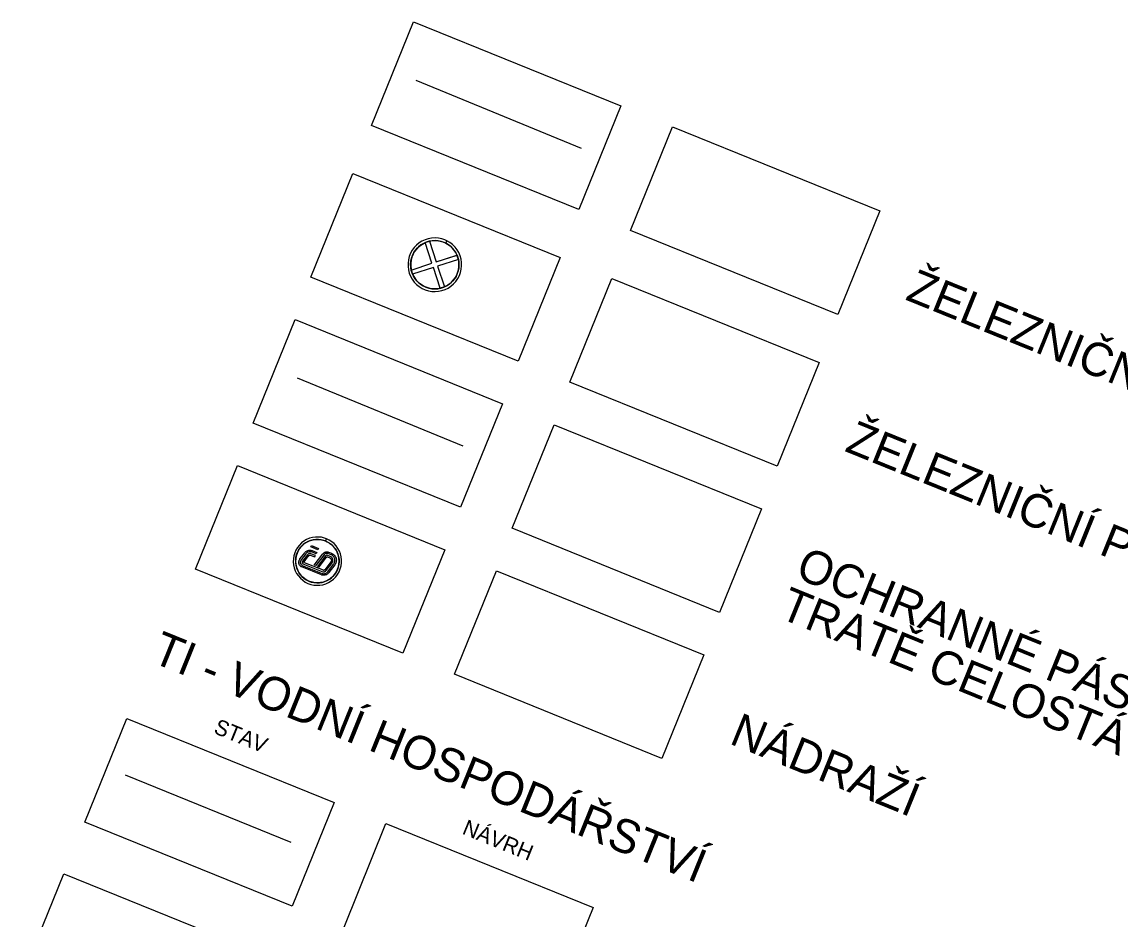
# Model space of a CAD drawing. Extents: x -522797 to -519326, y -1191143 to -1184078.
# Drawn here: x -521504.4 to -521013.3, y -1189290.3 to -1188889.1 of the extents above; entities that cross this region are included whole.
import ezdxf

# ---------------------------------------------------------------- set-up
doc = ezdxf.new("R2010")
doc.units = 0
for name, color, linetype in [('Implicitní', 7, 'Continuous'), ('nadrazi_s', 7, 'Continuous'), ('OP_zel_trate_s', 7, 'Continuous'), ('zel_celostat_s', 7, 'Continuous'), ('zel_prejezd_s', 7, 'Continuous')]:
    doc.layers.add(name, color=color, linetype=linetype)

msp = doc.modelspace()

# ---------------------------------------------------------------- linework, layer by layer
at = {"layer": 'Implicitní'}
msp.add_line((-521458.26, -1189225.9), (-521384.11, -1189255.95), dxfattribs=at)
for points in [[(-521329.25, -1188889.13), (-521236.57, -1188926.69), (-521255.35, -1188973.03), (-521348.03, -1188935.47)], [(-521213.4, -1188936.09), (-521120.73, -1188973.65), (-521139.51, -1189019.99), (-521232.18, -1188982.42)], [(-521356.37, -1188956.93), (-521263.68, -1188994.47), (-521282.45, -1189040.81), (-521375.14, -1189003.27)], [(-521240.51, -1189003.86), (-521147.82, -1189041.4), (-521166.6, -1189087.74), (-521259.28, -1189050.2)], [(-521382.14, -1189022.23), (-521289.49, -1189059.85), (-521308.3, -1189106.18), (-521400.95, -1189068.56)], [(-521266.32, -1189069.26), (-521173.67, -1189106.88), (-521192.48, -1189153.2), (-521285.13, -1189115.58)], [(-521407.91, -1189087.53), (-521315.26, -1189125.15), (-521334.07, -1189171.48), (-521426.72, -1189133.86)], [(-521292.1, -1189134.56), (-521199.44, -1189172.18), (-521218.25, -1189218.51), (-521310.91, -1189180.88)], [(-521457.41, -1189200.67), (-521364.73, -1189238.23), (-521383.51, -1189284.57), (-521476.19, -1189247.01)], [(-521341.56, -1189247.62), (-521248.89, -1189285.18), (-521267.67, -1189331.52), (-521360.34, -1189293.96)], [(-521485.58, -1189270.18), (-521392.9, -1189307.74), (-521411.68, -1189354.08), (-521504.36, -1189316.52)]]:
    msp.add_lwpolyline(points, close=True, dxfattribs=at)
at = {"layer": 'nadrazi_s'}
for points in [[(-521368.23, -1189120.23), (-521369.08, -1189119.93), (-521370.41, -1189119.61), (-521371.76, -1189119.47), (-521373.13, -1189119.5), (-521374.48, -1189119.69), (-521375.8, -1189120.06), (-521377.06, -1189120.59), (-521378.24, -1189121.28), (-521379.33, -1189122.11), (-521380.3, -1189123.07), (-521381.14, -1189124.14), (-521381.84, -1189125.31), (-521382.39, -1189126.56), (-521382.78, -1189127.88), (-521382.99, -1189129.22), (-521383.04, -1189130.59), (-521382.91, -1189131.95), (-521382.62, -1189133.28), (-521382.15, -1189134.57), (-521381.53, -1189135.78), (-521380.76, -1189136.91), (-521379.85, -1189137.93), (-521378.82, -1189138.83), (-521377.69, -1189139.6), (-521376.47, -1189140.21), (-521375.18, -1189140.66), (-521373.84, -1189140.95), (-521372.48, -1189141.07), (-521371.12, -1189141.01), (-521369.77, -1189140.79), (-521368.46, -1189140.39), (-521367.21, -1189139.83), (-521366.05, -1189139.12), (-521364.98, -1189138.27), (-521364.03, -1189137.29), (-521363.21, -1189136.2), (-521362.53, -1189135.01), (-521362.01, -1189133.75), (-521361.65, -1189132.43), (-521361.46, -1189131.08), (-521361.44, -1189129.71), (-521361.6, -1189128.35), (-521361.93, -1189127.03), (-521362.42, -1189125.75), (-521363.07, -1189124.55), (-521363.86, -1189123.44), (-521364.79, -1189122.43), (-521365.84, -1189121.56), (-521366.99, -1189120.82), (-521368.22, -1189120.23)], [(-521363.21, -1189133.88), (-521362.82, -1189132.71), (-521362.59, -1189131.5), (-521362.51, -1189130.27), (-521362.59, -1189129.05), (-521362.82, -1189127.84), (-521363.2, -1189126.67), (-521363.73, -1189125.56), (-521364.39, -1189124.52), (-521365.17, -1189123.58), (-521366.07, -1189122.74), (-521367.07, -1189122.02), (-521368.15, -1189121.44), (-521369.3, -1189120.99), (-521370.49, -1189120.69), (-521371.72, -1189120.55), (-521372.95, -1189120.56), (-521374.16, -1189120.73), (-521375.35, -1189121.05), (-521376.49, -1189121.52), (-521377.56, -1189122.12), (-521378.54, -1189122.86), (-521379.43, -1189123.71), (-521380.2, -1189124.67), (-521380.84, -1189125.72), (-521381.34, -1189126.84), (-521381.7, -1189128.02), (-521381.91, -1189129.23), (-521381.96, -1189130.46), (-521381.86, -1189131.69), (-521381.6, -1189132.89), (-521381.2, -1189134.05), (-521380.65, -1189135.15), (-521379.96, -1189136.17), (-521379.16, -1189137.1), (-521378.24, -1189137.92), (-521377.23, -1189138.62), (-521376.13, -1189139.18), (-521374.98, -1189139.6), (-521373.78, -1189139.87), (-521372.55, -1189139.99), (-521371.32, -1189139.95), (-521370.11, -1189139.76), (-521368.93, -1189139.41), (-521367.8, -1189138.92), (-521366.74, -1189138.29), (-521365.78, -1189137.53), (-521364.91, -1189136.66), (-521364.16, -1189135.69), (-521363.54, -1189134.62), (-521363.21, -1189133.88)], [(-521368.62, -1189121.23), (-521367.88, -1189121.57), (-521366.82, -1189122.19), (-521365.85, -1189122.93), (-521364.97, -1189123.8), (-521364.21, -1189124.77), (-521363.58, -1189125.82), (-521363.09, -1189126.95), (-521362.75, -1189128.13), (-521362.55, -1189129.35), (-521362.52, -1189130.58), (-521362.63, -1189131.8), (-521362.9, -1189133), (-521363.32, -1189134.16), (-521363.88, -1189135.25), (-521364.58, -1189136.26), (-521365.4, -1189137.18), (-521366.33, -1189137.99), (-521367.35, -1189138.67), (-521368.45, -1189139.22), (-521369.61, -1189139.63), (-521370.81, -1189139.89), (-521372.04, -1189139.99), (-521373.27, -1189139.94), (-521374.48, -1189139.73), (-521375.65, -1189139.37), (-521376.78, -1189138.87), (-521377.82, -1189138.23), (-521378.79, -1189137.46), (-521379.64, -1189136.58), (-521380.38, -1189135.59), (-521380.98, -1189134.52), (-521381.45, -1189133.38), (-521381.77, -1189132.2), (-521381.94, -1189130.98), (-521381.95, -1189129.75), (-521381.81, -1189128.53), (-521381.51, -1189127.33), (-521381.07, -1189126.19), (-521380.48, -1189125.1), (-521379.77, -1189124.11), (-521378.93, -1189123.2), (-521377.98, -1189122.42), (-521376.95, -1189121.75), (-521375.84, -1189121.23), (-521374.67, -1189120.85), (-521373.46, -1189120.61), (-521372.23, -1189120.54), (-521371.01, -1189120.62), (-521369.8, -1189120.85), (-521368.63, -1189121.23)], [(-521368.63, -1189121.23), (-521368.23, -1189120.23)], [(-521368.22, -1189120.23), (-521368.62, -1189121.23)], [(-521380.03, -1189129.3), (-521377.89, -1189126.52)], [(-521377.36, -1189126.95), (-521379.5, -1189129.71)], [(-521376.68, -1189127.45), (-521378.85, -1189130.26)], [(-521378.19, -1189130.52), (-521376.17, -1189127.9)], [(-521377.89, -1189126.52), (-521377.65, -1189126.25), (-521377.39, -1189126), (-521377.1, -1189125.79), (-521376.79, -1189125.62), (-521376.47, -1189125.49), (-521376.13, -1189125.4), (-521375.8, -1189125.35), (-521375.46, -1189125.35), (-521375.12, -1189125.39), (-521374.8, -1189125.47), (-521374.64, -1189125.53)], [(-521374.89, -1189126.16), (-521375.13, -1189126.08), (-521375.38, -1189126.03), (-521375.63, -1189126.02), (-521375.88, -1189126.04), (-521376.14, -1189126.1), (-521376.38, -1189126.18), (-521376.62, -1189126.3), (-521376.85, -1189126.44), (-521377.06, -1189126.61), (-521377.25, -1189126.81), (-521377.36, -1189126.95)], [(-521375.21, -1189126.94), (-521375.21, -1189126.94), (-521375.34, -1189126.9), (-521375.49, -1189126.87), (-521375.63, -1189126.87), (-521375.78, -1189126.88), (-521375.93, -1189126.92), (-521376.07, -1189126.97), (-521376.22, -1189127.04), (-521376.35, -1189127.13), (-521376.48, -1189127.23), (-521376.6, -1189127.35), (-521376.68, -1189127.45)], [(-521376.17, -1189127.91), (-521376.17, -1189127.9), (-521376.12, -1189127.84), (-521376.07, -1189127.77), (-521376.01, -1189127.72), (-521375.95, -1189127.67), (-521375.89, -1189127.63), (-521375.83, -1189127.6), (-521375.76, -1189127.57), (-521375.7, -1189127.55), (-521375.64, -1189127.55), (-521375.58, -1189127.55), (-521375.52, -1189127.56), (-521375.47, -1189127.57)], [(-521375.47, -1189127.57), (-521373.38, -1189128.41)], [(-521373.13, -1189127.77), (-521375.21, -1189126.94)], [(-521372.07, -1189125.2), (-521375.2, -1189123.94), (-521374.94, -1189123.31), (-521371.81, -1189124.56), (-521372.07, -1189125.2)], [(-521372.81, -1189126.99), (-521374.89, -1189126.16)], [(-521374.64, -1189125.53), (-521372.56, -1189126.36)], [(-521374.64, -1189125.53), (-521374.64, -1189125.53)], [(-521373.62, -1189132.02), (-521369.75, -1189126.99)], [(-521373.38, -1189128.41), (-521373.13, -1189127.77)], [(-521369.22, -1189127.41), (-521372.97, -1189132.28)], [(-521372.56, -1189126.36), (-521372.81, -1189126.99)], [(-521368.56, -1189127.95), (-521372.15, -1189132.61)], [(-521369.75, -1189126.99), (-521369.57, -1189126.78), (-521369.36, -1189126.59), (-521369.14, -1189126.43), (-521368.9, -1189126.3), (-521368.66, -1189126.19), (-521368.4, -1189126.12), (-521368.14, -1189126.09), (-521367.88, -1189126.08), (-521367.62, -1189126.12), (-521367.37, -1189126.18), (-521367.25, -1189126.22)], [(-521367.5, -1189126.85), (-521367.66, -1189126.8), (-521367.84, -1189126.77), (-521368.01, -1189126.76), (-521368.19, -1189126.78), (-521368.36, -1189126.81), (-521368.53, -1189126.87), (-521368.7, -1189126.95), (-521368.86, -1189127.05), (-521369, -1189127.17), (-521369.14, -1189127.31), (-521369.22, -1189127.41)], [(-521367.82, -1189127.64), (-521367.85, -1189127.63), (-521367.91, -1189127.61), (-521367.98, -1189127.61), (-521368.05, -1189127.61), (-521368.12, -1189127.62), (-521368.19, -1189127.65), (-521368.26, -1189127.68), (-521368.33, -1189127.72), (-521368.39, -1189127.76), (-521368.45, -1189127.82), (-521368.51, -1189127.88), (-521368.56, -1189127.95)], [(-521366.46, -1189128.18), (-521367.81, -1189127.64)], [(-521366.14, -1189127.4), (-521367.5, -1189126.85)], [(-521367.25, -1189126.22), (-521365.89, -1189126.77)], [(-521365, -1189131.57), (-521364.81, -1189131.29), (-521364.65, -1189130.98), (-521364.54, -1189130.66), (-521364.47, -1189130.32), (-521364.44, -1189129.98), (-521364.45, -1189129.64), (-521364.51, -1189129.3), (-521364.61, -1189128.97), (-521364.75, -1189128.66), (-521364.92, -1189128.36), (-521365.14, -1189128.1), (-521365.38, -1189127.86), (-521365.66, -1189127.65), (-521365.96, -1189127.48), (-521366.14, -1189127.4)], [(-521365.89, -1189126.77), (-521365.5, -1189126.95), (-521365.14, -1189127.18), (-521364.81, -1189127.46), (-521364.52, -1189127.77), (-521364.27, -1189128.12), (-521364.07, -1189128.5), (-521363.91, -1189128.9), (-521363.81, -1189129.32), (-521363.76, -1189129.74), (-521363.77, -1189130.17), (-521363.83, -1189130.6), (-521363.94, -1189131.01), (-521364.1, -1189131.41), (-521364.31, -1189131.78), (-521364.46, -1189131.99)], [(-521379.26, -1189132.85), (-521379.49, -1189132.74), (-521379.71, -1189132.6), (-521379.91, -1189132.43), (-521380.08, -1189132.24), (-521380.23, -1189132.02), (-521380.36, -1189131.78), (-521380.45, -1189131.53), (-521380.52, -1189131.26), (-521380.55, -1189130.99), (-521380.55, -1189130.71), (-521380.52, -1189130.43), (-521380.46, -1189130.16), (-521380.37, -1189129.89), (-521380.25, -1189129.64), (-521380.11, -1189129.4), (-521380.03, -1189129.3)], [(-521379.51, -1189129.73), (-521379.61, -1189129.89), (-521379.71, -1189130.06), (-521379.78, -1189130.24), (-521379.83, -1189130.43), (-521379.87, -1189130.62), (-521379.88, -1189130.82), (-521379.87, -1189131.01), (-521379.84, -1189131.19), (-521379.79, -1189131.37), (-521379.72, -1189131.54), (-521379.63, -1189131.7), (-521379.53, -1189131.84), (-521379.41, -1189131.97), (-521379.27, -1189132.08), (-521379.12, -1189132.17), (-521379.01, -1189132.22)], [(-521370.36, -1189136.42), (-521379.26, -1189132.86)], [(-521378.85, -1189130.26), (-521378.89, -1189130.33), (-521378.93, -1189130.41), (-521378.97, -1189130.49), (-521378.99, -1189130.58), (-521379.01, -1189130.66), (-521379.03, -1189130.75), (-521379.03, -1189130.83), (-521379.03, -1189130.91), (-521379.02, -1189130.99), (-521379, -1189131.07), (-521378.97, -1189131.14), (-521378.94, -1189131.21), (-521378.9, -1189131.27), (-521378.86, -1189131.32), (-521378.81, -1189131.37), (-521378.75, -1189131.41), (-521378.69, -1189131.44)], [(-521379.01, -1189132.23), (-521370.11, -1189135.79)], [(-521378.69, -1189131.44), (-521369.79, -1189135)], [(-521378.07, -1189130.96), (-521378.09, -1189130.95), (-521378.12, -1189130.93), (-521378.15, -1189130.91), (-521378.17, -1189130.88), (-521378.2, -1189130.85), (-521378.21, -1189130.82), (-521378.23, -1189130.79), (-521378.24, -1189130.76), (-521378.25, -1189130.72), (-521378.25, -1189130.69), (-521378.24, -1189130.65), (-521378.24, -1189130.62), (-521378.22, -1189130.58), (-521378.21, -1189130.55), (-521378.19, -1189130.52)], [(-521369.54, -1189134.37), (-521378.07, -1189130.95)], [(-521372.97, -1189132.28), (-521373.62, -1189132.02)], [(-521372.15, -1189132.61), (-521371.49, -1189132.87)], [(-521371.49, -1189132.87), (-521368.11, -1189128.47)], [(-521366.21, -1189130.64), (-521368.79, -1189133.99)], [(-521368.3, -1189134.47), (-521365.67, -1189131.06)], [(-521368.11, -1189128.47), (-521368.11, -1189128.47), (-521368.08, -1189128.44), (-521368.05, -1189128.42), (-521368.02, -1189128.4), (-521367.99, -1189128.38), (-521367.96, -1189128.37), (-521367.92, -1189128.37), (-521367.89, -1189128.36), (-521367.85, -1189128.37), (-521367.82, -1189128.37), (-521367.78, -1189128.38)], [(-521367.78, -1189128.39), (-521366.71, -1189128.81)], [(-521367.64, -1189135.01), (-521365, -1189131.57)], [(-521364.46, -1189131.99), (-521367.11, -1189135.42)], [(-521366.71, -1189128.81), (-521366.63, -1189128.85), (-521366.5, -1189128.92), (-521366.38, -1189129.02), (-521366.27, -1189129.12), (-521366.18, -1189129.24), (-521366.1, -1189129.37), (-521366.04, -1189129.5), (-521365.99, -1189129.65), (-521365.97, -1189129.8), (-521365.96, -1189129.94), (-521365.98, -1189130.09), (-521366.01, -1189130.24), (-521366.06, -1189130.38), (-521366.13, -1189130.52), (-521366.21, -1189130.64)], [(-521365.67, -1189131.06), (-521365.59, -1189130.94), (-521365.47, -1189130.74), (-521365.38, -1189130.52), (-521365.32, -1189130.29), (-521365.29, -1189130.06), (-521365.29, -1189129.82), (-521365.31, -1189129.59), (-521365.37, -1189129.36), (-521365.45, -1189129.14), (-521365.57, -1189128.93), (-521365.7, -1189128.74), (-521365.86, -1189128.56), (-521366.05, -1189128.41), (-521366.24, -1189128.28), (-521366.46, -1189128.18)], [(-521367.11, -1189135.42), (-521367.34, -1189135.69), (-521367.61, -1189135.94), (-521367.9, -1189136.15), (-521368.21, -1189136.32), (-521368.53, -1189136.45), (-521368.86, -1189136.54), (-521369.2, -1189136.59), (-521369.54, -1189136.59), (-521369.88, -1189136.55), (-521370.2, -1189136.47), (-521370.36, -1189136.41)], [(-521370.11, -1189135.78), (-521369.87, -1189135.86), (-521369.62, -1189135.91), (-521369.37, -1189135.92), (-521369.11, -1189135.9), (-521368.86, -1189135.84), (-521368.61, -1189135.76), (-521368.38, -1189135.64), (-521368.15, -1189135.5), (-521367.94, -1189135.33), (-521367.75, -1189135.13), (-521367.64, -1189134.99)], [(-521369.79, -1189135), (-521369.79, -1189135), (-521369.65, -1189135.04), (-521369.51, -1189135.07), (-521369.36, -1189135.07), (-521369.22, -1189135.06), (-521369.07, -1189135.02), (-521368.92, -1189134.97), (-521368.78, -1189134.9), (-521368.65, -1189134.81), (-521368.52, -1189134.71), (-521368.4, -1189134.59), (-521368.3, -1189134.47)], [(-521368.79, -1189133.99), (-521368.88, -1189134.1), (-521368.93, -1189134.17), (-521368.99, -1189134.22), (-521369.05, -1189134.27), (-521369.11, -1189134.31), (-521369.17, -1189134.34), (-521369.23, -1189134.37), (-521369.3, -1189134.39), (-521369.36, -1189134.39), (-521369.42, -1189134.39), (-521369.48, -1189134.38), (-521369.54, -1189134.37)]]:
    msp.add_lwpolyline(points, dxfattribs=at)
at = {"layer": 'OP_zel_trate_s'}
msp.add_line((-521381.23, -1189048.23), (-521307.26, -1189078.71), dxfattribs=at)
at = {"layer": 'zel_celostat_s'}
msp.add_line((-521328.29, -1188915.09), (-521254.32, -1188945.56), dxfattribs=at)
at = {"layer": 'zel_prejezd_s'}
for points in [[(-521314.28, -1188987), (-521315.19, -1188986.58), (-521316.63, -1188986.1), (-521318.12, -1188985.8), (-521319.64, -1188985.69), (-521321.15, -1188985.78), (-521322.65, -1188986.05), (-521324.09, -1188986.52), (-521325.47, -1188987.16), (-521326.75, -1188987.96), (-521327.92, -1188988.93), (-521328.97, -1188990.03), (-521329.86, -1188991.26), (-521330.59, -1188992.59), (-521331.15, -1188994), (-521331.53, -1188995.47), (-521331.71, -1188996.98), (-521331.71, -1188998.5), (-521331.51, -1189000), (-521331.13, -1189001.47), (-521330.56, -1189002.88), (-521329.82, -1189004.21), (-521328.92, -1189005.43), (-521327.87, -1189006.53), (-521326.69, -1189007.48), (-521325.4, -1189008.28), (-521324.02, -1189008.92), (-521322.57, -1189009.37), (-521321.08, -1189009.63), (-521319.56, -1189009.71), (-521318.05, -1189009.59), (-521316.56, -1189009.28), (-521315.12, -1189008.79), (-521313.76, -1189008.12), (-521312.49, -1189007.29), (-521311.34, -1189006.3), (-521310.32, -1189005.17), (-521309.46, -1189003.93), (-521308.75, -1189002.58), (-521308.23, -1189001.16), (-521307.88, -1188999.68), (-521307.73, -1188998.17), (-521307.76, -1188996.65), (-521307.99, -1188995.15), (-521308.41, -1188993.69), (-521309, -1188992.29), (-521309.77, -1188990.98), (-521310.7, -1188989.78), (-521311.77, -1188988.71), (-521312.97, -1188987.77), (-521314.28, -1188987)], [(-521314.82, -1188988.07), (-521314.04, -1188988.51), (-521312.92, -1188989.3), (-521311.92, -1188990.23), (-521311.04, -1188991.27), (-521310.3, -1188992.42), (-521309.7, -1188993.65), (-521309.27, -1188994.95), (-521309.01, -1188996.29), (-521308.92, -1188997.65), (-521309, -1188999.02), (-521309.25, -1189000.36), (-521309.67, -1189001.66), (-521310.25, -1189002.9), (-521310.98, -1189004.05), (-521311.85, -1189005.11), (-521312.85, -1189006.04), (-521313.96, -1189006.84), (-521315.16, -1189007.5), (-521316.43, -1189007.99), (-521317.75, -1189008.33), (-521319.11, -1189008.49), (-521320.48, -1189008.48), (-521321.83, -1189008.3), (-521323.15, -1189007.95), (-521324.42, -1189007.44), (-521325.61, -1189006.77), (-521326.7, -1189005.95), (-521327.69, -1189005.01), (-521328.55, -1189003.94), (-521329.27, -1189002.78), (-521329.83, -1189001.54), (-521330.23, -1189000.23), (-521330.47, -1188998.89), (-521330.53, -1188997.52), (-521330.42, -1188996.16), (-521330.14, -1188994.82), (-521329.7, -1188993.53), (-521329.09, -1188992.3), (-521328.33, -1188991.17), (-521327.44, -1188990.13), (-521326.42, -1188989.22), (-521325.3, -1188988.44), (-521324.09, -1188987.81), (-521322.8, -1188987.34), (-521321.47, -1188987.04), (-521320.11, -1188986.9), (-521318.75, -1188986.94), (-521317.4, -1188987.15), (-521316.08, -1188987.53), (-521314.83, -1188988.07)], [(-521310.09, -1189002.6), (-521309.55, -1189001.35), (-521309.17, -1189000.03), (-521308.96, -1188998.69), (-521308.92, -1188997.32), (-521309.06, -1188995.96), (-521309.36, -1188994.63), (-521309.83, -1188993.35), (-521310.46, -1188992.13), (-521311.24, -1188991.01), (-521312.15, -1188989.99), (-521313.19, -1188989.1), (-521314.32, -1188988.34), (-521315.55, -1188987.73), (-521316.84, -1188987.29), (-521318.18, -1188987.01), (-521319.54, -1188986.9), (-521320.9, -1188986.96), (-521322.25, -1188987.19), (-521323.56, -1188987.59), (-521324.8, -1188988.16), (-521325.96, -1188988.88), (-521327.03, -1188989.73), (-521327.98, -1188990.72), (-521328.79, -1188991.82), (-521329.46, -1188993.01), (-521329.97, -1188994.27), (-521330.33, -1188995.59), (-521330.51, -1188996.95), (-521330.52, -1188998.31), (-521330.35, -1188999.67), (-521330.02, -1189001), (-521329.52, -1189002.27), (-521328.87, -1189003.47), (-521328.07, -1189004.57), (-521327.13, -1189005.57), (-521326.08, -1189006.44), (-521324.93, -1189007.18), (-521323.69, -1189007.76), (-521322.39, -1189008.18), (-521321.05, -1189008.43), (-521319.68, -1189008.51), (-521318.32, -1189008.42), (-521316.98, -1189008.15), (-521315.68, -1189007.72), (-521314.45, -1189007.13), (-521313.3, -1189006.39), (-521312.26, -1189005.51), (-521311.33, -1189004.51), (-521310.54, -1189003.39), (-521310.09, -1189002.6)], [(-521321, -1188997.06), (-521324.02, -1188987.77), (-521322.11, -1188987.15)], [(-521320.99, -1188997.06), (-521324.01, -1188987.78), (-521322.11, -1188987.16)], [(-521322.11, -1188987.15), (-521319.09, -1188996.44)], [(-521322.11, -1188987.16), (-521319.08, -1188996.44)], [(-521314.83, -1188988.07), (-521314.28, -1188987)], [(-521314.28, -1188987), (-521314.82, -1188988.07)], [(-521319.09, -1188996.44), (-521309.81, -1188993.42), (-521309.19, -1188995.32)], [(-521319.08, -1188996.44), (-521309.8, -1188993.42), (-521309.18, -1188995.32)], [(-521309.19, -1188995.32), (-521318.47, -1188998.34)], [(-521309.18, -1188995.32), (-521318.46, -1188998.34)], [(-521330.28, -1189000.08), (-521321, -1188997.06)], [(-521320.38, -1188998.96), (-521329.66, -1189001.98), (-521330.28, -1189000.08)], [(-521330.27, -1189000.08), (-521320.99, -1188997.06)], [(-521320.37, -1188998.96), (-521329.65, -1189001.99), (-521330.27, -1189000.08)], [(-521317.35, -1189008.24), (-521320.38, -1188998.96)], [(-521317.35, -1189008.25), (-521320.37, -1188998.96)], [(-521318.47, -1188998.34), (-521315.45, -1189007.62), (-521317.35, -1189008.24)], [(-521318.46, -1188998.34), (-521315.44, -1189007.63), (-521317.35, -1189008.25)]]:
    msp.add_lwpolyline(points, dxfattribs=at)

# ---------------------------------------------------------------- texts
at = {"layer": 'Implicitní'}
for s, height, rotation, p in [('ŽELEZNIČNÍ TRAŤ CELOSTÁTNÍ', 15, 337.9379, (-521109.76, -1189013.16)), ('ŽELEZNIČNÍ PŘEJEZD', 15, 337.9487, (-521136.86, -1189080.91)), ('OCHRANNÉ PÁSMO ŽELEZNIČNÍ ', 15, 337.9005, (-521159.08, -1189137.4)), ('TRATĚ CELOSTÁTNÍ', 15, 337.9005, (-521166.39, -1189155.39)), ('TI - VODNÍ HOSPODÁŘSTVÍ', 15, 337.9379, (-521447.08, -1189175.18)), ('STAV', 7, 337.9379, (-521419.05, -1189207.05)), ('NÁDRAŽÍ', 15, 337.9005, (-521188.51, -1189211.7)), ('NÁVRH', 7, 337.9379, (-521307.9, -1189252.09))]:
    msp.add_text(s, height=height, rotation=rotation, dxfattribs=at).set_placement(p)

doc.saveas('drawing.dxf')
